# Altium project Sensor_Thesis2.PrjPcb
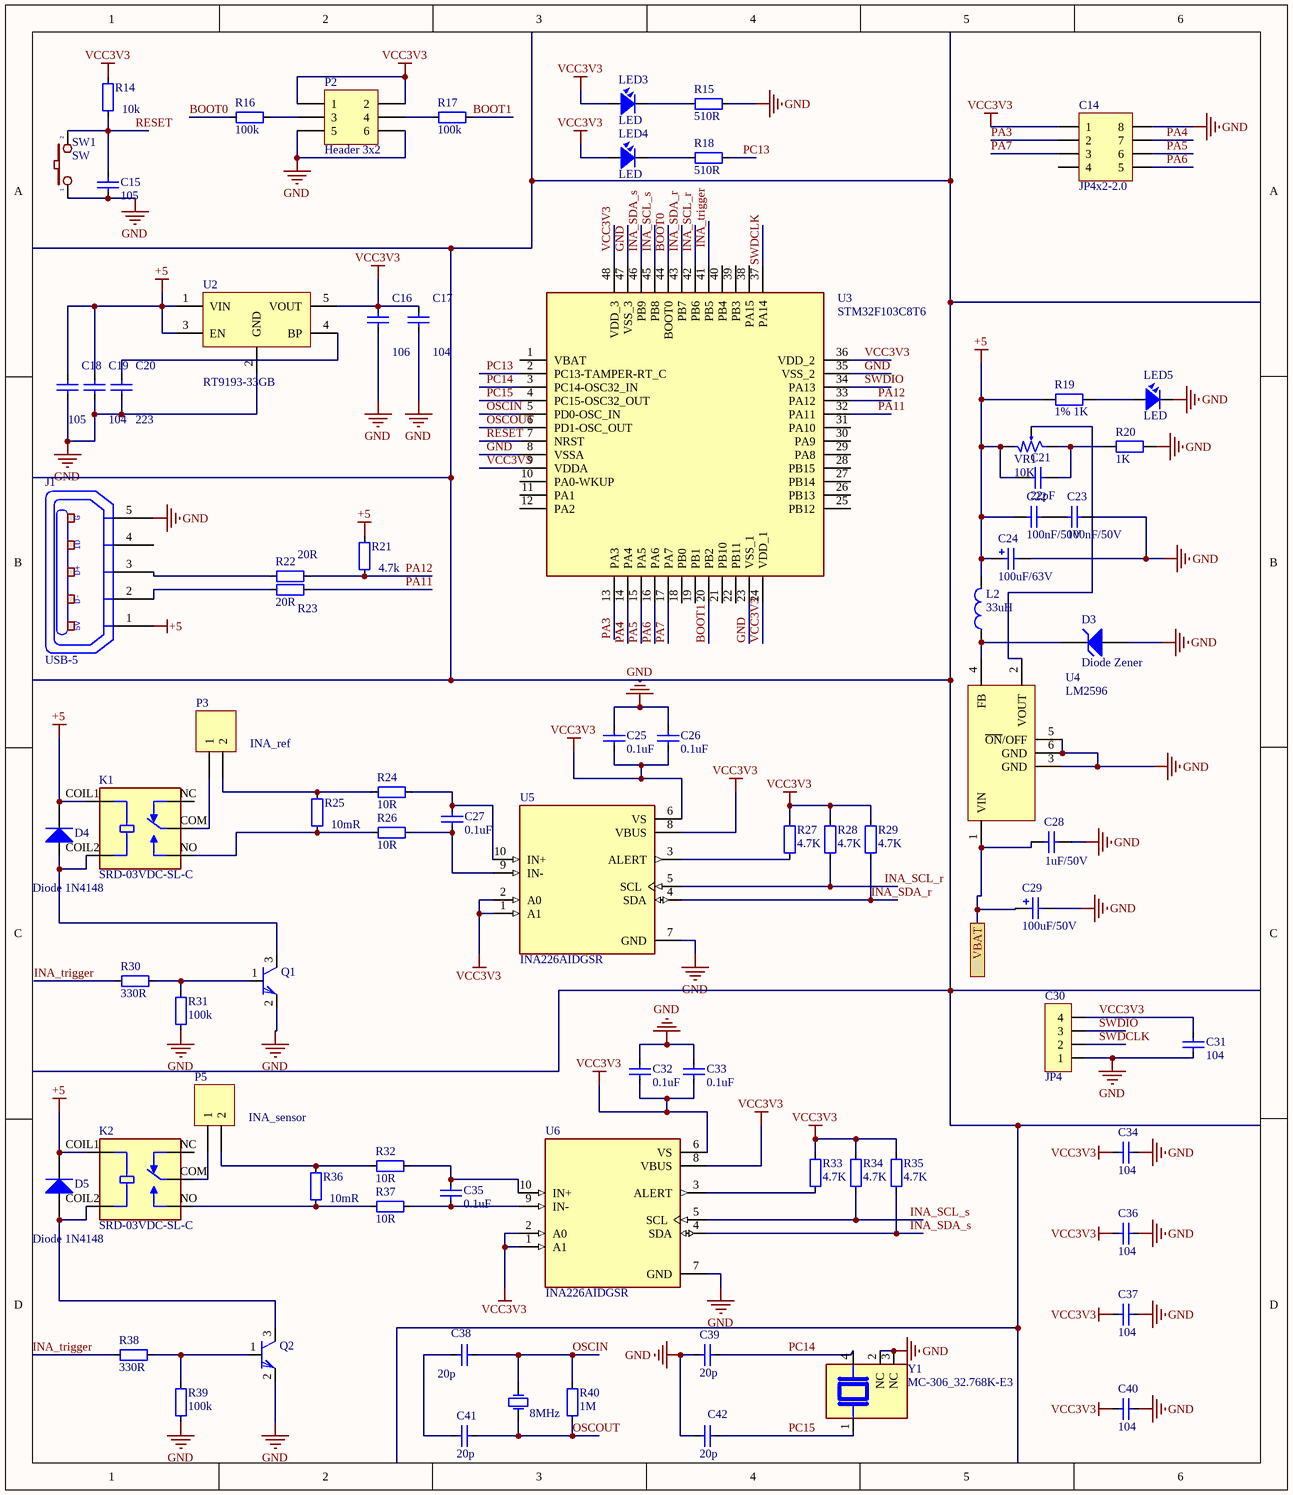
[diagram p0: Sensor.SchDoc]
1 sheet, 80 parts. Net scope: flat (ports and power ports of the same name join across sheets).
Board file: Sensor.PcbDoc

## Sheet Sensor.SchDoc
size 241 x 279 mm; SheetNumber: 3; SheetTotal: 3

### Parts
C14  JP4x2-2.0  [J4-C2T]
C15  105  [CAP_0805]
C16  106  [CAP_0805]
C17  104  [CAP_0805]
C18  105  [CAP_0805]
C19  104  [CAP_0805]
C20  223  [CAP_0805]
C21  22pF  [CAP_0805]
C22  100nF/50V  [CAP_0805]
C23  100nF/50V  [CAP_0805]
C24  value 100uF/63V  [CAP-ALU-SMD-C]  (hidden comment: Cap Pol SMD)
C25  0.1uF  [CAP_0805]
C26  0.1uF  [CAP_0805]
C27  0.1uF  [CAP_0805]
C28  1uF/50V  [CAP_0805]
C29  value 100uF/50V  [CAP-ALU-SMD-C]  (hidden comment: Cap Pol SMD)
C30  JP4  [JP4-D1C]
C31  104  [CAP_0805]
C32  0.1uF  [CAP_0805]
C33  0.1uF  [CAP_0805]
C34  104  [CAP_0805]
C35  0.1uF  [CAP_0805]
C36  104  [CAP_0805]
C37  104  [CAP_0805]
C38  20p  [CAP_0805]
C39  20p  [CAP_0805]
C40  104  [CAP_0805]
C41  20p  [CAP_0805]
C42  20p  [CAP_0805]
D3  Diode Zener  [DIODE_ZENER_SMD]
D4  Diode 1N4148  [DO-35]
D5  Diode 1N4148  [DO-35]
J1  USB-5  [USB-M1]
K1  SRD-03VDC-SL-C  [RELAY_SRD-03VDC-SL-C]
K2  SRD-03VDC-SL-C  [RELAY_SRD-03VDC-SL-C]
L2  33uH  [Inductor_SMD]
LED3  LED  [LED-0805-Blue]
LED4  LED  [LED-0805-Blue]
LED5  LED  [LED0805]
P2  Header 3x2  [Header 3x2]
P3  INA_ref  [KF2-5.08]
P5  INA_sensor  [KF2-5.08]
Q1  C1815  [SOT23 [C1815]]  (value not drawn)
Q2  C1815  [SOT23 [C1815]]  (value not drawn)
R14  10k  [RES-SMD-0805]
R15  510R  [RES-SMD-0805]
R16  100k  [RES-SMD-0805]
R17  100k  [RES-SMD-0805]
R18  510R  [RES-SMD-0805]
R19  1% 1K  [SM-0805]
R20  1K  [SM-0805]
R21  4.7k  [RES-SMD-0805]
R22  20R  [RES-SMD-0805]
R23  20R  [RES-SMD-0805]
R24  10R  [RES-SMD-0805]
R25  10mR  [RES-SMD-0805]
R26  10R  [RES-SMD-0805]
R27  4.7K  [RES-SMD-0805]
R28  4.7K  [RES-SMD-0805]
R29  4.7K  [RES-SMD-0805]
R30  330R  [RES-SMD-0805]
R31  100k  [RES-SMD-0805]
R32  10R  [RES-SMD-0805]
R33  4.7K  [RES-SMD-0805]
R34  4.7K  [RES-SMD-0805]
R35  4.7K  [RES-SMD-0805]
R36  10mR  [RES-SMD-0805]
R37  10R  [RES-SMD-0805]
R38  330R  [RES-SMD-0805]
R39  100k  [RES-SMD-0805]
R40  1M  [RES-SMD-0805]
SW1  SW  [SW2]
U2  RT9193-33GB  [SOT23-5AL]
U3  STM32F103C8T6  [LQFP-48_19.6_393_58X11_SMD]
U4  LM2596  [TO263-5]
U5  INA226AIDGSR  [SOP50P490X110-10N]
U6  INA226AIDGSR  [SOP50P490X110-10N]
VR1  10K  [VR1]
Y1  MC-306_32.768K-E3  [XTAL_MC-306_32.768K-E3]
Y2  8MHz  [XTAL_SMD]

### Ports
VBAT

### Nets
+5: C18.2 C19.2 C21.2 C22.2 C24.1 D4.2(K) D5.2(K) J1.1(P1) K1.COIL1 K2.COIL1 L2.2 R19.2 R21.1 U2.1(VIN) U2.3(EN) VR1.1
GND: C14.8 C15.1 C16.1 C17.1 C18.1 C19.1 C20.1 C23.1 C24.2 C25.2 C26.2 C28.1 C29.2 C30.1 C31.1 C32.2 C33.2 C34.1 C36.1 C37.1 C39.1 C40.1 C42.1 D3.1(A) J1.5(P5) LED5.2 P2.5 P2.6 Q1.2(E) Q2.2(E) R15.1 R20.1 R31.1 R39.1 SW1.1 U2.2(GND) U3.8(VSSA) U3.23(VSS_1) U3.35(VSS_2) U3.47(VSS_3) U4.3(GND) U4.5(~{ON}/OFF) U4.6(GND) U5.7(GND) U6.7(GND) Y1.2(NC) Y1.3(NC)
VCC3V3: C14.1 C16.2 C17.2 C25.1 C26.1 C30.4 C31.2 C32.1 C33.1 C34.2 C36.2 C37.2 C40.2 LED3.1 LED4.1 P2.1 P2.2 R14.1 R27.2 R28.2 R29.2 R33.2 R34.2 R35.2 U2.5(VOUT) U3.9(VDDA) U3.24(VDD_1) U3.36(VDD_2) U3.48(VDD_3) U5.1(A1) U5.2(A0) U5.6(VS) U5.8(VBUS) U6.1(A1) U6.2(A0) U6.6(VS) U6.8(VBUS)
BOOT0: R16.2 U3.44(BOOT0)
BOOT1: R17.1 U3.20(PB2)
INA_SCL_r: R28.1 U3.42(PB6) U5.5(SCL)
INA_SCL_s: R34.1 U3.45(PB8) U6.5(SCL)
INA_SDA_r: R29.1 U3.43(PB7) U5.4(SDA)
INA_SDA_s: R35.1 U3.46(PB9) U6.4(SDA)
INA_trigger: R30.1 R38.1 U3.41(PB5)
OSCIN: C38.2 R40.2 U3.5(PD0-OSC_IN) Y2.2(OSC2)
OSCOUT: C41.2 R40.1 U3.6(PD1-OSC_OUT) Y2.1(OSC1)
PA3: C14.2 U3.13(PA3)
PA4: C14.7 U3.14(PA4)
PA5: C14.6 U3.15(PA5)
PA6: C14.5 U3.16(PA6)
PA7: C14.3 U3.17(PA7)
PA11: R23.2 U3.32(PA11)
PA12: R21.2 R22.2 U3.33(PA12)
PC13: R18.1 U3.2(PC13-TAMPER-RT_C)
PC14: C39.2 U3.3(PC14-OSC32_IN) Y1.4
PC15: C42.2 U3.4(PC15-OSC32_OUT) Y1.1
RESET: C15.2 R14.2 SW1.2 U3.7(NRST)
SWDCLK: C30.2 U3.37(PA14)
SWDIO: C30.3 U3.34(PA13)
NetC20_2: C20.2 U2.4(BP)
NetC21_1: C21.1 R20.2 VR1.3
NetC22_1: C22.1 C23.2
NetC27_1: C27.1 R24.2 U5.10(IN+)
NetC27_2: C27.2 R26.1 U5.9(IN-)
NetC28_2: C28.2 C29.1 U4.1(VIN) ; port VBAT
NetC35_1: C35.1 R32.2 U6.10(IN+)
NetC35_2: C35.2 R37.1 U6.9(IN-)
NetC38_1: C38.1 C41.1
NetD3_2: D3.2(K) L2.1 U4.4(FB)
NetD4_1: D4.1(A) K1.COIL2 Q1.3(C)
NetD5_1: D5.1(A) K2.COIL2 Q2.3(C)
NetJ1_2: J1.2(P2) R23.1
NetJ1_3: J1.3(P3) R22.1
NetK1_COM: K1.COM P3.1
NetK1_NO: K1.NO R25.2 R26.2
NetK2_COM: K2.COM P5.1
NetK2_NO: K2.NO R36.2 R37.2
NetLED3_2: LED3.2 R15.2
NetLED4_2: LED4.2 R18.2
NetLED5_1: LED5.1 R19.1
NetP2_3: P2.3 R16.1
NetP2_4: P2.4 R17.2
NetP3_2: P3.2 R24.1 R25.1
NetP5_2: P5.2 R32.1 R36.1
NetQ1_1: Q1.1(B) R30.2 R31.2
NetQ2_1: Q2.1(B) R38.2 R39.2
NetR27_1: R27.1 U5.3(ALERT)
NetR33_1: R33.1 U6.3(ALERT)
NetU4_2: U4.2(VOUT) VR1.2

Not connected (* = marked no-connect by the designer): C14 4; J1 4(P4); K1 NC; K2 NC; U3 1(VBAT) 10(PA0-WKUP) 11(PA1) 12(PA2) 18(PB0) 19(PB1) 21(PB10) 22(PB11) 25(PB12) 26(PB13) 27(PB14) 28(PB15) 29(PA8) 30(PA9) 31(PA10) 38(PA15) 39(PB3) 40(PB4)

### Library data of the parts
C14 = JP4x2-2.0: WR-PHD 2.00 mm Dual Pin Header; Manufacturer: W¨¹rth Elektronik eiSos GmbH; partNo: 62000821121; ComponentLink1 Description: Manufacturer; ComponentLink2 Description: Datasheet; NoPins: 08
C15-C20 C25-C27 C31-C42 = CapSMD: Capacitor; Value: 33p
C21-C23 C28 = Cap SMD 1206
C24 C29 = Cap Pol SMD: Polarized Capacitor (Radial)
C30 = JP4: WR-PHD 2.54 mm Angled Socket Header; Manufacturer: W¨¹rth Elektronik eiSos GmbH; partNo: 613004143121; ComponentLink1 Description: Manufacturer; ComponentLink2 Description: Datasheet; NoPins: 04
D3 = Diode Zener: Zener Diode
D4 D5 = Diode 1N4148: High Conductance Fast Diode
J1 = USB-5: Manufacturer: FCI; Manufacturer Part Number: 10118193-0001LF; Connector Type: USB - micro B; Number of Contacts: 5; Gender: Receptacle; Specifications: USB 2.0; .Creator: MM; .Checked PCB: RF
K1 K2 = SRD-03VDC-SL-C: Relays General Purpose Non Latching 3VDC SPDT 10A (250VAC) Max 5PIN; MF: Songle Relay
L2 = L1: Inductor; Value: 150 mH
LED3-LED5 = LED: LED Single colour Green and Red; Value: LED 3 ly Single Colour
P2 = Header 3x2: Header, 6-Pin, 2-Row
P3 P5 = Header 2: Header, 2-Pin
Q1 Q2 = C1815: Q2SC1815; PSpiceTemplate: Q^@REFDES %c %b %e @MODEL; Vendor: Digikey
R14-R18 R21-R40 = Resistor - SMD: Resistor; Manufacturer: Generic Components; Class: Passive
R19 R20 = RM: Resistor SMD
SW1 = SW2: Switch button 2 pin; Value: SW chip 2 pin
U2 = RT9193: 1A Regulator
U3 = IC_STM32F103C8T6: ARM® Cortex®-M3 STM32F1 Microcontroller IC 32-Bit 72MHz 64KB (64K x 8) FLASH 48-LQFP (7x7) /; Manufacturer: STMicroelectronics; Alternate Part Number-1: NA
U4 = LM2596: 1A Regulator
U5 U6 = INA226AIDGSR: 36V, 16-bit, ultra-precise i2c output current/voltage/power monitor w/alert; MF: Texas Instruments
VR1 = VR1: Var Resistor; Value: VR 10K
Y1 = MC-306_32.768K-E3: CRYSTAL 32.7680KHZ 6PF SMD; MF: EPSON; MP: MC-306 32.768K-E3
Y2 = XTAL: Crystal Oscillator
